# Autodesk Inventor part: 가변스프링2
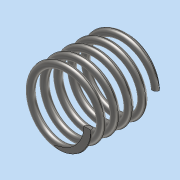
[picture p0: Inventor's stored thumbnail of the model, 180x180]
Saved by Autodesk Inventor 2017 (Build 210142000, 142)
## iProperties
Part Number: 가변스프링2
Material: 스테인레스 스틸
Document SubType Name: Modeling
Designer: MRC
Density: 8 g/cm^3
Appearance: 반연마
Mass: 6.96277 g
Surface Area: 17.6923 cm^2
Volume: 0.870346 cm^3
Author: MRC
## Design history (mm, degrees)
sketch "스케치1"
  geometry: L1 (0, 0)-(0, 19.5); L2 (0, 19.5)-(9, 19.5); L3 (0, 0)-(9, 0); C1 r 1 at (9, 0)
  constraints: 6 end point, 2 horizontal, 1 centre point, 1 coincident, 1 vertical
  dimensions: "d0" = 19.5 distance of L1.start L1.end (derived); "d1" = 9 distance of L1.end L2.end; "d2" = 9 distance of L1.start L3.end; "d3" = 2 diameter of C1
feature "코일1" sketch "스케치1" pitch "d4" = 10; turns "d6" = 5; dims "d5" = 19.5 (= d0), "d7" = 0, angle "d8" = 90 deg, angle "d9" = 90 deg, "d10" = 0, "d11" = 0
sketch "스케치2"
  geometry: L1 (19.5, 21.748)-(0, 21.748); L2 (0, 21.748)-(0, -21.748); L3 (0, -21.748)-(19.5, -21.748); L4 (19.5, -21.748)-(19.5, 21.748); 2 further points
  constraints: 8 end point, 2 midpoint, 2 parallel, 1 coincident, 1 horizontal, 1 perpendicular
  dimensions: "d12" = 19.5 distance of L2.end L3.end (= d0); "d13" = 43.49633 distance of L3.end L1.start
extrude "돌출1" sketch "스케치2" stored distance "d14" = 0; taper "d15" = 0 deg
node "솔리드1"
